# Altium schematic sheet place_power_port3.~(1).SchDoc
size A4
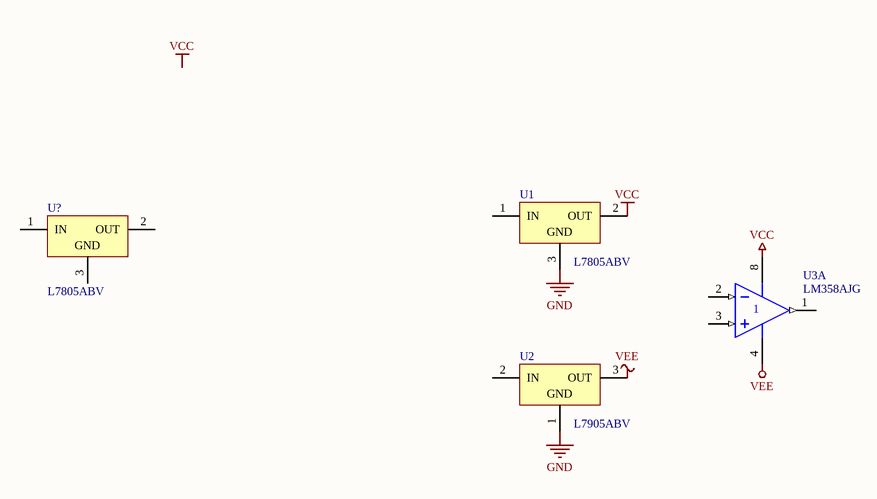
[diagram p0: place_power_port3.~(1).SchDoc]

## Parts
U1  L7805ABV  [TO220ABN]
U2  L7905ABV  [TO220V]
U3  LM358AJG  [JG008]  (part A of 2)
U?  L7805ABV  [TO220ABN]

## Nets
GND: U1.3(GND) U2.1(GND)
VCC: U1.2(OUT) U3.8(V+)
VEE: U2.3(OUT) U3.4(V-)

Not connected (* = marked no-connect by the designer): U1 1(IN); U2 2(IN); U3 1(OUT) 2(IN-) 3(IN+); U? 1(IN) 2(OUT) 3(GND)

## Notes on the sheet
- Labels drawn without touching a wire or pin: VCC

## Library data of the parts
U1 U? = L7805ABV: Precision 1A Regulator; Note: Tab is connected to pin 3 (GND).
U2 = L7905ABV: ?2%Negative Voltage Regulator; Note: Tab is connected to pin 3 (IN).
U3 = LM358AJG: Dual Operational Amplifier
